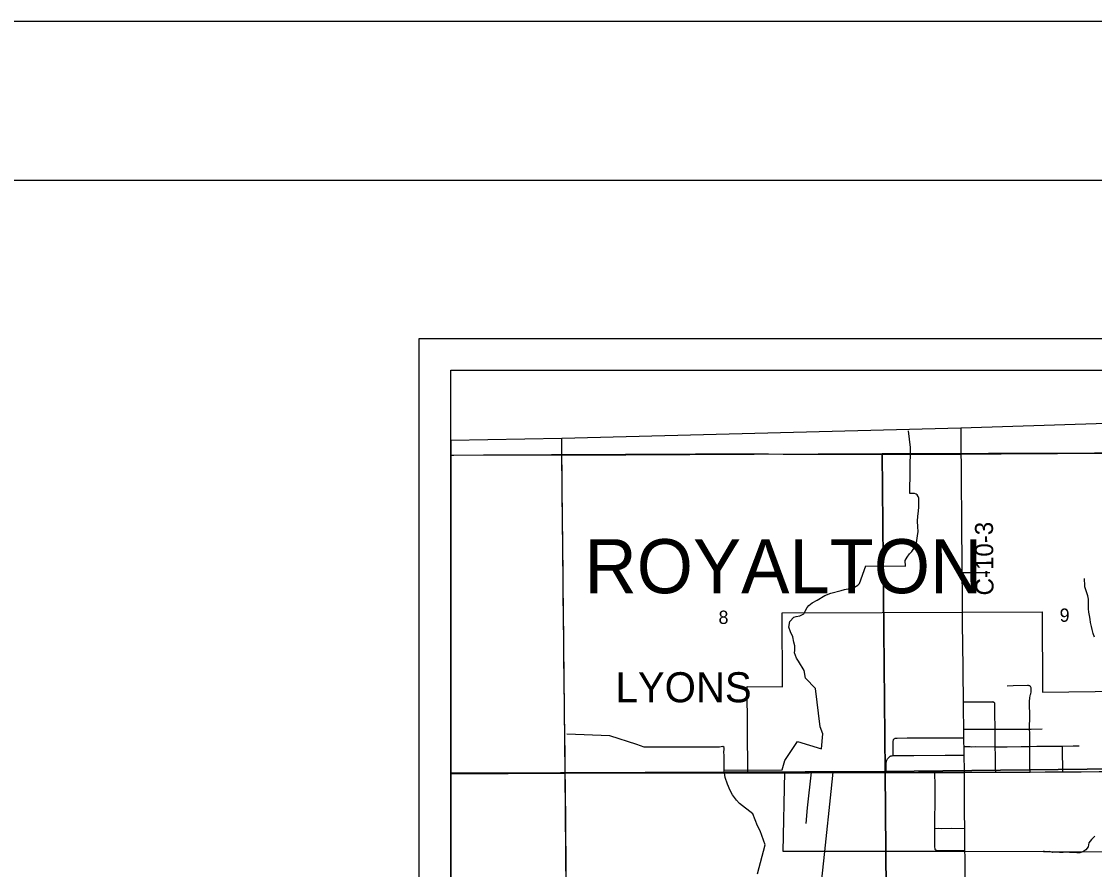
# Model space of a CAD drawing. Extents: x 0 to 34, y 0 to 22.
# Drawn here: x 22.163 to 25.546, y 19.326 to 22 of the extents above; entities that cross this region are included whole.
import ezdxf

# ---------------------------------------------------------------- set-up
doc = ezdxf.new("R2010")
doc.units = 0
for name, color, linetype in [('GM_X_City_Street', 7, 'Continuous'), ('GM_X_Corporation', 7, 'Continuous'), ('GM_X_Corporation_Text', 7, 'Continuous'), ('GM_X_County', 7, 'Continuous'), ('GM_X_County_Road', 7, 'Continuous'), ('GM_X_County_Road_Text', 7, 'Continuous'), ('GM_X_Minor_River', 7, 'Continuous'), ('GM_X_Rail_Line', 7, 'Continuous'), ('GM_X_Section', 7, 'Continuous'), ('GM_X_Section_Text', 7, 'Continuous'), ('GM_X_State_Route', 7, 'Continuous'), ('GM_X_Township_Road', 7, 'Continuous'), ('GM_X_Township_Text', 7, 'Continuous'), ('SC_Scratch1', 7, 'Continuous'), ('SH_Border', 7, 'Continuous'), ('SH_Cut_Line', 7, 'Continuous'), ('SH_Data', 7, 'Continuous')]:
    doc.layers.add(name, color=color, linetype=linetype)

msp = doc.modelspace()

# ---------------------------------------------------------------- linework, layer by layer
at = {"layer": 'GM_X_City_Street'}
for points in [[(25.342, 19.8113), (25.3419, 19.8484), (25.3418, 19.8555), (25.3418, 19.8587), (25.3421, 19.8637), (25.3425, 19.8672), (25.3438, 19.8731), (25.3447, 19.8774), (25.3452, 19.8794), (25.3463, 19.8861), (25.3466, 19.8881), (25.3469, 19.8901), (25.347, 19.8926), (25.347, 19.8947), (25.3469, 19.8967), (25.3463, 19.8992), (25.3455, 19.9013), (25.3444, 19.9029), (25.3436, 19.9037), (25.343, 19.9043), (25.3423, 19.9046), (25.3414, 19.905), (25.3401, 19.9053), (25.3383, 19.9056), (25.3353, 19.9056), (25.2895, 19.9045), (25.2713, 19.904)], [(25.133, 19.8545), (25.1686, 19.8543), (25.2065, 19.8548), (25.2191, 19.855), (25.2222, 19.8549), (25.2253, 19.8545)], [(25.2348, 19.6327), (25.2344, 19.6482), (25.2341, 19.6607), (25.2339, 19.6857), (25.2336, 19.7131), (25.2331, 19.7681), (25.2325, 19.8209), (25.2325, 19.8471), (25.2324, 19.8481), (25.2324, 19.8488), (25.2318, 19.8501), (25.2309, 19.8511), (25.2296, 19.8522), (25.2288, 19.8529), (25.228, 19.8535), (25.2272, 19.854), (25.2265, 19.8542), (25.2253, 19.8545)], [(25.3433, 19.6331), (25.3426, 19.6474), (25.3428, 19.6799), (25.3424, 19.7142), (25.3423, 19.727), (25.3421, 19.7562), (25.3418, 19.7683), (25.342, 19.8113)], [(25.1341, 19.7679), (25.1775, 19.7679), (25.2331, 19.7681), (25.2352, 19.7681), (25.2899, 19.7683), (25.3418, 19.7683), (25.3464, 19.7682), (25.3818, 19.7694)], [(24.9116, 19.6848), (24.9116, 19.7005), (24.9116, 19.7162), (24.9116, 19.7287), (24.9117, 19.7302), (24.9119, 19.7318), (24.9122, 19.7332), (24.9126, 19.7346), (24.9131, 19.7358), (24.914, 19.7371), (24.9148, 19.738), (24.9163, 19.7392)], [(24.9163, 19.7392), (24.9181, 19.7398), (24.9196, 19.74), (24.9214, 19.7401), (24.9245, 19.7403), (24.9553, 19.7405), (25.0692, 19.7408), (25.1186, 19.741), (25.1345, 19.741)], [(25.1351, 19.7137), (25.1542, 19.7134), (25.1598, 19.7131), (25.172, 19.7134), (25.2336, 19.7131), (25.2712, 19.713), (25.3148, 19.7134), (25.3424, 19.7142), (25.3642, 19.7144), (25.4015, 19.715), (25.4233, 19.7152), (25.4456, 19.7152), (25.4793, 19.7153), (25.498, 19.7155)], [(25.4468, 19.6336), (25.4463, 19.656), (25.4459, 19.684), (25.4456, 19.7152)], [(24.8898, 19.6322), (24.8891, 19.6436), (24.89, 19.6607), (24.8905, 19.6655), (24.891, 19.667), (24.8921, 19.6707), (24.8939, 19.6744), (24.8956, 19.6768), (24.8977, 19.6794), (24.8998, 19.6814), (24.9014, 19.6828), (24.9029, 19.6837), (24.9045, 19.6842), (24.9079, 19.6847), (24.9116, 19.6848)], [(24.9116, 19.6848), (24.9317, 19.6851), (24.9652, 19.6853), (24.9771, 19.6856), (25.0757, 19.6861), (25.122, 19.6863), (25.1358, 19.6863)], [(24.637, 19.4711), (24.642, 19.5202), (24.6542, 19.6326)], [(25.0442, 19.3886), (25.0438, 19.3895), (25.0436, 19.3905), (25.0435, 19.3913), (25.0435, 19.3919), (25.0433, 19.396), (25.0431, 19.405), (25.0429, 19.4272), (25.0426, 19.452), (25.0426, 19.4556), (25.0426, 19.4767), (25.0439, 19.5448), (25.0436, 19.5881), (25.043, 19.6325)], [(25.0426, 19.4556), (25.0546, 19.4558), (25.0641, 19.4555), (25.0953, 19.4557), (25.1371, 19.4552)], [(25.0442, 19.3886), (25.0446, 19.388), (25.0452, 19.3875), (25.046, 19.3871), (25.0469, 19.3866), (25.0478, 19.3864), (25.049, 19.3862), (25.0509, 19.3861), (25.0533, 19.386), (25.0658, 19.3858), (25.1034, 19.3858), (25.1285, 19.3854), (25.1378, 19.3854)]]:
    msp.add_lwpolyline(points, dxfattribs=at)
at = {"layer": 'GM_X_Corporation'}
msp.add_lwpolyline([(24.5652, 19.3826), (24.57, 19.633), (24.4536, 19.6328), (24.4515, 19.9027), (24.5624, 19.9018), (24.5612, 20.1354), (24.8773, 20.1361), (25.1302, 20.1369), (25.3811, 20.1379), (25.3819, 19.8854), (25.6319, 19.8878), (25.6346, 19.636), (25.6339, 19.3801), (25.1376, 19.3828), (24.6959, 19.3828)], close=True, dxfattribs=at)
at = {"layer": 'GM_X_County'}
msp.add_lwpolyline([(28.8862, 20.7941), (27.8891, 20.7835), (26.8843, 20.7634), (25.88, 20.7414), (25.1253, 20.7174), (23.8668, 20.6853), (23.5167, 20.6789)], dxfattribs=at)
at = {"layer": 'GM_X_County_Road'}
for p, q in [((25.1345, 19.741), (25.1341, 19.7679)), ((25.1358, 19.6863), (25.1351, 19.7137)), ((25.136, 19.6113), (25.136, 19.6332)), ((25.1378, 19.3854), (25.1371, 19.4552))]:
    msp.add_line(p, q, dxfattribs=at)
for points in [[(25.1263, 20.6355), (25.1262, 20.6414), (25.1259, 20.6912), (25.1255, 20.7168)], [(23.8673, 20.6343), (23.8672, 20.6518), (23.867, 20.6847)], [(23.8777, 19.6313), (23.8772, 19.6789), (23.8771, 19.6975), (23.8767, 19.738), (23.8745, 19.9245), (23.8734, 19.9927), (23.8728, 20.0611), (23.8715, 20.1886), (23.8708, 20.229), (23.8708, 20.257), (23.8689, 20.4373), (23.8683, 20.4995), (23.8678, 20.571), (23.8673, 20.6343)], [(25.1294, 20.2619), (25.1293, 20.2801), (25.1288, 20.3268), (25.1281, 20.3735), (25.1267, 20.6071), (25.1263, 20.6355)], [(25.1304, 20.1363), (25.1298, 20.1884), (25.1294, 20.2619)], [(25.133, 19.8545), (25.1311, 20.0455), (25.1306, 20.0889), (25.1304, 20.1363)], [(25.1341, 19.7679), (25.134, 19.7824), (25.1335, 19.8197), (25.133, 19.8545)], [(25.1351, 19.7137), (25.1346, 19.7243), (25.1346, 19.7332), (25.1345, 19.741)], [(25.136, 19.6332), (25.1361, 19.65), (25.1358, 19.6747), (25.1358, 19.6863)], [(23.8901, 18.2832), (23.89, 18.2923), (23.8882, 18.4509), (23.886, 18.6623), (23.8844, 18.8488), (23.8839, 18.9265), (23.8836, 18.9483), (23.8833, 18.9825), (23.8824, 19.0602), (23.8818, 19.1348), (23.881, 19.2623), (23.8805, 19.3369), (23.8781, 19.5887), (23.8777, 19.6313)], [(25.1364, 19.5503), (25.1365, 19.5596), (25.1367, 19.5689), (25.136, 19.6064), (25.136, 19.6113)], [(25.1371, 19.4552), (25.1366, 19.5066), (25.1363, 19.5472), (25.1364, 19.5503)], [(25.1379, 19.3812), (25.1379, 19.3822), (25.1378, 19.3854)], [(25.1452, 18.632), (25.1445, 18.6646), (25.1437, 18.7733), (25.1433, 18.8012), (25.1429, 18.8477), (25.1424, 18.8944), (25.1408, 19.0747), (25.1401, 19.1582), (25.1393, 19.2357), (25.1387, 19.3165), (25.1382, 19.3693), (25.1379, 19.3812)]]:
    msp.add_lwpolyline(points, dxfattribs=at)
at = {"layer": 'GM_X_Minor_River'}
for points in [[(24.3791, 19.639), (24.5619, 19.6403), (24.5702, 19.6698), (24.6102, 19.729), (24.6858, 19.7066), (24.6897, 19.7532), (24.6813, 19.7753), (24.6671, 19.8961), (24.6348, 19.9287), (24.6313, 19.9538), (24.6127, 19.9824), (24.6063, 19.9927), (24.6008, 20.0087), (24.6013, 20.0167), (24.6018, 20.025), (24.6014, 20.0311), (24.5989, 20.0429), (24.5953, 20.0596), (24.5879, 20.0756), (24.5831, 20.0905), (24.586, 20.1075), (24.5986, 20.1214), (24.6059, 20.1233), (24.6173, 20.1258), (24.6295, 20.1322), (24.6345, 20.1404), (24.6403, 20.1525), (24.6453, 20.1578), (24.6564, 20.1672), (24.6717, 20.1754), (24.6961, 20.1903), (24.7151, 20.197), (24.7474, 20.2057), (24.7581, 20.2083), (24.7748, 20.2119), (24.79, 20.2159), (24.7999, 20.2223), (24.8053, 20.2279), (24.8257, 20.2835), (24.9504, 20.2827), (24.9498, 20.3001), (24.9552, 20.3107), (24.9633, 20.3209), (24.9702, 20.3288), (24.9791, 20.3412), (24.9853, 20.3559), (24.9886, 20.3779), (24.9899, 20.3912), (24.9893, 20.406), (24.9887, 20.4238), (24.9897, 20.4405), (24.9914, 20.4553), (24.9923, 20.4693), (24.992, 20.48), (24.9926, 20.4963), (24.9904, 20.5024), (24.9874, 20.5077), (24.9844, 20.5092), (24.9791, 20.5112), (24.9639, 20.511), (24.9659, 20.6563), (24.9597, 20.7092)], [(25.5465, 20.0587), (25.5425, 20.0705), (25.5392, 20.0823), (25.5367, 20.0925), (25.5334, 20.1047), (25.5324, 20.115), (25.5302, 20.1271), (25.5284, 20.1374), (25.527, 20.1473), (25.5275, 20.1571), (25.5276, 20.167), (25.527, 20.178), (25.5256, 20.1886), (25.5223, 20.1982), (25.5186, 20.2081), (25.5161, 20.2176), (25.5158, 20.2271), (25.5151, 20.2369), (25.5145, 20.2434)], [(24.4836, 19.312), (24.5085, 19.404), (24.4919, 19.4478), (24.4841, 19.4631), (24.469, 19.5012), (24.4273, 19.5342), (24.4172, 19.5446), (24.4052, 19.561), (24.3978, 19.5751), (24.3889, 19.5946), (24.3815, 19.6155), (24.3791, 19.6375), (24.3792, 19.6842), (24.3779, 19.6971), (24.3787, 19.7039), (24.3784, 19.7108), (24.3746, 19.7135), (24.364, 19.7121), (24.127, 19.7121), (24.1032, 19.7203), (24.0179, 19.7477), (23.8829, 19.7525)], [(25.5476, 19.431), (25.5372, 19.4208), (25.5288, 19.4099), (25.5268, 19.3978), (25.5194, 19.3876), (25.5099, 19.382), (25.5004, 19.3787), (25.4905, 19.3788), (25.4792, 19.3793), (25.4678, 19.3798), (25.4576, 19.3806), (25.4473, 19.3796), (25.436, 19.3793), (25.4261, 19.3809), (25.4147, 19.3799), (25.4041, 19.3827), (25.3931, 19.382), (25.386, 19.384)]]:
    msp.add_lwpolyline(points, dxfattribs=at)
at = {"layer": 'GM_X_Rail_Line'}
msp.add_lwpolyline([(23.5167, 19.628), (23.8789, 19.6294), (24.6464, 19.6305), (25.1346, 19.6322), (26.4299, 19.6404), (26.8953, 19.6404), (26.9248, 19.6506), (26.9689, 19.6865), (27.5616, 20.0799), (27.7012, 20.176), (27.7435, 20.1963), (27.7849, 20.2), (27.8935, 20.211), (28.1535, 20.2337)], dxfattribs=at)
at = {"layer": 'GM_X_Section'}
for points in [[(23.8673, 20.632), (24.877, 20.6376), (24.8865, 19.6346), (23.8779, 19.6309)], [(24.877, 20.6376), (25.8814, 20.6407), (25.8865, 19.646), (24.8865, 19.6346)], [(23.5167, 20.6311), (23.5167, 19.6297), (23.8779, 19.6309), (23.8673, 20.632)], [(23.5167, 19.6297), (23.5167, 18.6363), (23.8857, 18.6369), (23.8779, 19.6309)], [(23.8779, 19.6309), (24.8865, 19.6346), (24.8949, 18.6346), (23.8857, 18.6369)], [(24.8865, 19.6346), (25.8865, 19.646), (25.8948, 18.6366), (24.8949, 18.6346)]]:
    msp.add_lwpolyline(points, close=True, dxfattribs=at)
at = {"layer": 'GM_X_State_Route'}
for points in [[(23.5167, 19.6298), (23.5966, 19.63), (23.7055, 19.6308), (23.8112, 19.6311), (23.8626, 19.6313)], [(23.8626, 19.6313), (23.8777, 19.6313), (23.9201, 19.6314), (23.9792, 19.6315), (24.0414, 19.6317), (24.144, 19.632), (24.1969, 19.632), (24.3151, 19.6321), (24.3493, 19.6321), (24.4021, 19.6323), (24.4528, 19.6323)], [(24.4528, 19.6323), (24.4538, 19.6323), (24.5141, 19.6322), (24.5702, 19.6325)], [(24.5702, 19.6325), (24.6542, 19.6326), (24.6879, 19.6326), (24.7225, 19.6326), (24.7344, 19.6326), (24.8298, 19.6322), (24.8898, 19.6322), (24.9229, 19.6322), (24.9912, 19.6324), (25.0091, 19.6324)], [(25.0091, 19.6324), (25.043, 19.6325), (25.0781, 19.6325), (25.0791, 19.6325)], [(25.0791, 19.6325), (25.136, 19.6332), (25.1688, 19.6329)], [(25.1688, 19.6329), (25.2115, 19.6326), (25.2348, 19.6327), (25.2389, 19.6327)], [(25.2389, 19.6327), (25.255, 19.6327), (25.2582, 19.6325), (25.2756, 19.6331), (25.338, 19.6331), (25.3433, 19.6331), (25.391, 19.6336), (25.4155, 19.6335), (25.4336, 19.6335), (25.4365, 19.6334), (25.4397, 19.6336), (25.4456, 19.6335), (25.4468, 19.6336), (25.5047, 19.6341), (25.5607, 19.6345), (25.6106, 19.6353), (25.6348, 19.6354)]]:
    msp.add_lwpolyline(points, dxfattribs=at)
at = {"layer": 'GM_X_Township_Road'}
msp.add_line((25.1294, 20.2619), (25.2167, 20.2623), dxfattribs=at)
for points in [[(25.1263, 20.6355), (25.2521, 20.6369), (25.3703, 20.6375), (25.4294, 20.638), (25.4636, 20.6383), (25.5289, 20.6389), (25.6596, 20.6391), (25.815, 20.6396), (25.88, 20.6401)], [(23.5167, 20.6328), (23.5266, 20.6328), (23.6198, 20.6332), (23.7503, 20.6336), (23.8342, 20.634), (23.8673, 20.6343)], [(23.8673, 20.6343), (23.8995, 20.6345), (24.0673, 20.6352), (24.1606, 20.6357), (24.288, 20.6362), (24.4061, 20.6366), (24.518, 20.6363), (24.5645, 20.6357), (24.6733, 20.6353), (24.6982, 20.6352), (24.7696, 20.6352), (24.8784, 20.6349), (24.9157, 20.6351), (25.0276, 20.6353), (25.1146, 20.6355), (25.1263, 20.6355)], [(24.6961, 19.3822), (24.7166, 19.5722), (24.7225, 19.6326)], [(24.6424, 18.632), (24.6421, 18.7037), (24.6418, 18.797), (24.641, 18.8593), (24.6413, 18.878), (24.6421, 18.8935), (24.6447, 18.9214), (24.6506, 18.9771), (24.6548, 19.0205), (24.6623, 19.0885), (24.6717, 19.1689), (24.6768, 19.2121), (24.6886, 19.3141), (24.6961, 19.3822)]]:
    msp.add_lwpolyline(points, dxfattribs=at)
at = {"layer": 'SC_Scratch1'}
msp.add_lwpolyline([(23.5167, 20.6789), (23.5167, 15.3175), (30.3167, 15.3175), (30.3167, 20.8109), (30.0181, 20.8047), (28.8862, 20.7941), (27.8891, 20.7835), (26.8843, 20.7634), (25.88, 20.7414), (25.1253, 20.7174), (23.8668, 20.6853)], close=True, dxfattribs=at)
at = {"layer": 'SH_Border'}
msp.add_lwpolyline([(1.5, 21.5), (33.5, 21.5), (33.5, 0.5), (1.5, 0.5)], close=True, dxfattribs=at)
at = {"layer": 'SH_Cut_Line'}
msp.add_lwpolyline([(0, 0), (34, 0), (34, 22), (0, 22)], close=True, dxfattribs=at)
at = {"layer": 'SH_Data'}
for points in [[(23.4167, 21), (30.4167, 21), (30.4167, 14), (23.4167, 14)], [(23.5167, 20.9), (30.3167, 20.9), (30.3167, 15.3175), (23.5167, 15.3175)]]:
    msp.add_lwpolyline(points, close=True, dxfattribs=at)

# ---------------------------------------------------------------- texts
at = {"layer": 'GM_X_Corporation_Text'}
msp.add_text('LYONS', height=0.0947, rotation=0, dxfattribs=at).set_placement((24.0362, 19.8532))
at = {"layer": 'GM_X_County_Road_Text'}
msp.add_text('C-10-3', height=0.05682, rotation=90.4801, dxfattribs=at).set_placement((25.2281, 20.1902))
at = {"layer": 'GM_X_Section_Text'}
for s, p in [('8', (24.361, 20.1002)), ('9', (25.4365, 20.1069))]:
    msp.add_text(s, height=0.0419, rotation=0, dxfattribs=at).set_placement(p)
at = {"layer": 'GM_X_Township_Text'}
msp.add_text('ROYALTON', height=0.17045, rotation=0, dxfattribs=at).set_placement((23.9385, 20.197))

doc.saveas('drawing.dxf')
